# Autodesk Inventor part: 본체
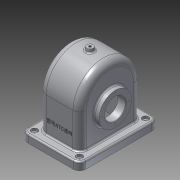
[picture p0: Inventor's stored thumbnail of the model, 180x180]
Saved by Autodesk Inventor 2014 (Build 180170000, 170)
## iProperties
Created: 2016-10
Part Number: 본체
Material: 알루미늄 6061
Document SubType Name: Modeling
Designer: USER
Density: 2.71 g/cm^3
Appearance: 알루미늄 - 평지
Mass: 1165.58 g
Surface Area: 1201.06 cm^2
Volume: 430.103 cm^3
Author: USER
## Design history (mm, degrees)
sketch "스케치2"
  geometry: L1 (-58, -80)-(58, -80); L2 (-58, 0)-(-58, -80); L3 (58, 0)-(58, -80); C1 r 52 at (0, 0); A1 r 58 centre (0, 0) between (58, 0) and (-58, 0); 1 further point
  constraints: 6 end point, 2 centre point, 2 point on circle, 2 tangent, 1 coincident, 1 parallel, 1 perpendicular
  dimensions: "d2" = 104 diameter of C1; "d4" = 6 radial gap between concentric circles of A1 C1; "d6" = 80 distance from line of L1 point (0, 0); "d8" = 138 dimension on A1 L1 (derived); "d9" = 58 distance from line of L2 point (0, 0) (derived); "d10" = 116 distance between parallel lines of L3 L2 (derived)
extrude "돌출1" new body sketch "스케치2" stored distance "d11" = 77; taper "d12" = 0 deg
fillet "모깎기1" dims "d13" = 13
sketch "스케치3"
  geometry: L1 (-58, -80)-(-58, 0) reference; L2 (58, 0)-(58, -80) reference; L3 (58, -80)-(-58, -80) reference; L4 (-52, 0)-(-52, -80); L5 (52, -80)-(52, 0); L6 (-52, -80)-(-52, -91.838); L7 (-52, -91.838)-(52, -91.838); L8 (52, -91.838)-(52, -80); A1 r 58 centre (0, 0) between (58, 0) and (-58, 0) reference; A2 r 52 centre (0, 0) between (52, 0) and (-52, 0); 1 further point
  constraints: 10 end point, 2 parallel, 2 point on circle, 2 point on line, 1 centre point, 1 perpendicular
  dimensions: "d14" = 6 radial gap between concentric circles of A1 A2; "d15" = 6 distance between parallel lines of L1 L4; "d16" = 6 distance between parallel lines of L2 L5
extrude "돌출2" cut sketch "스케치3" stored distance "d17" = 67; taper "d18" = 0 deg
fillet "모깎기2" dims "d19" = 8
sketch "스케치4"
  geometry: L1 (64, -13)-(64, -103) reference; L2 (51, 0)-(0, 0) reference; L3 (-13, -103)-(-13, -13) reference; L4 (0, -116)-(51, -116) reference; L5 (-29.5, -133)-(80.5, -133); L6 (80.5, -133)-(80.5, 17); L7 (80.5, 17)-(-29.5, 17); L8 (-29.5, 17)-(-29.5, -133); L9 (-29.5, -133)-(80.5, 17); L10 (80.5, -133)-(-29.5, 17); A1 r 13 centre (51, -103) between (51, -116) and (64, -103) reference; A2 r 13 centre (51, -13) between (64, -13) and (51, 0) reference; A3 r 13 centre (0, -13) between (0, 0) and (-13, -13) reference; A4 r 13 centre (0, -103) between (-13, -103) and (0, -116) reference; 3 further points
  constraints: 12 end point, 3 midpoint, 2 parallel, 1 coincident, 1 horizontal, 1 perpendicular
  dimensions: "d20" = 150 distance of L5.end L6.end; "d21" = 110 distance of L6.end L7.end
extrude "돌출3" join sketch "스케치4" distance "d22" = 15; taper "d23" = 0 deg
fillet "모깎기3" dims "d24" = 12
sketch "스케치5"
  geometry: A1 r 12 centre (-68.5, 5) between (-68.5, 17) and (-80.5, 5) reference; A2 r 12 centre (-68.5, -121) between (-80.5, -121) and (-68.5, -133) reference; A3 r 12 centre (17.5, -121) between (17.5, -133) and (29.5, -121) reference; A4 r 12 centre (17.5, 5) between (29.5, 5) and (17.5, 17) reference; 1 further point
hole "구멍1" sketch "스케치5" at (17.5, 5), (17.5, -121), (-68.5, -121), (-68.5, 5) diameter "d25" = 5; stored, may be unused: countersink angle "d29" = 90 deg, drill point angle "d31" = 118 deg; dims "d26" = 6, "d27" = 12, "d28" = 5, "d30" = 8
sketch "스케치6"
  geometry: L1 (-25.5, 58)-(25.5, 58) reference; L2 (38.5, 45)-(38.5, -65) reference; L3 (38.5, -65)-(55, -65) reference; L4 (55, -65)-(55, -80) reference; L5 (55, -80)-(33.5, -80) reference; L6 (33.5, -80)-(33.5, 44) reference; L7 (25.5, 52)-(-25.5, 52) reference; L8 (-33.5, 44)-(-33.5, -80) reference; L9 (-33.5, -80)-(-55, -80) reference; L10 (-55, -80)-(-55, -65) reference; L11 (-55, -65)-(-38.5, -65) reference; L12 (-38.5, -65)-(-38.5, 45) reference; L13 (-7.058, 58)-(-6, 64); L14 (-6, 64)-(0, 64); L15 (0, 0)-(0, 86.343); L16 (-7.058, 58)-(0, 58); L17 (-7.058, 58)-(-7.729, 54.192); L18 (-7.729, 54.192)-(0, 54.192); A1 r 13 centre (-25.5, 45) between (-25.5, 58) and (-38.5, 45) reference; A2 r 13 centre (25.5, 45) between (38.5, 45) and (25.5, 58) reference; A3 r 8 centre (25.5, 44) between (33.5, 44) and (25.5, 52) reference; A4 r 8 centre (-25.5, 44) between (-25.5, 52) and (-33.5, 44) reference
  constraints: 12 end point, 4 point on line, 2 perpendicular, 1 collinear, 1 midpoint, 1 parallel
  dimensions: "d32" = 33.5 distance from line of L8 L15.end (derived); "d33" = 100 deg angle of L1 L13; "d35" = 12 diameter of L13.end L15; "d36" = 144 distance between parallel lines of L5 L14
revolve "회전1" sketch "스케치6" stored, may be unused: angle "d37" = 90 deg
sketch "스케치7"
  geometry: L1 (38.5, -15)-(43.5, -15); L2 (-43, -80)-(-55, -80) reference; L3 (-25.5, 58)-(-7.058, 58) reference; L4 (-7.058, 58)-(-6, 64) reference; L5 (-6, 64)-(6, 64) reference; L6 (6, 64)-(7.058, 58) reference; L7 (7.058, 58)-(25.5, 58) reference; L8 (38.5, 45)-(38.5, -65) reference; L9 (38.5, -65)-(55, -65) reference; L10 (55, -65)-(55, -80) reference; L11 (55, -80)-(33.5, -80) reference; L12 (33.5, -80)-(33.5, 44) reference; L13 (25.5, 52)-(-25.5, 52) reference; L14 (-33.5, 44)-(-33.5, -80) reference; L15 (-33.5, -80)-(-55, -80) reference; L16 (-55, -80)-(-55, -65) reference; L17 (-55, -65)-(-38.5, -65) reference; L18 (-38.5, -65)-(-38.5, 45) reference; L19 (43.5, -15)-(43.5, 22.5); L20 (43.5, 22.5)-(38.5, 22.5); L21 (38.5, 22.5)-(38.5, -15); A1 r 13 centre (-25.5, 45) between (-25.5, 58) and (-38.5, 45) reference; A2 r 13 centre (25.5, 45) between (38.5, 45) and (25.5, 58) reference; A3 r 8 centre (25.5, 44) between (33.5, 44) and (25.5, 52) reference; A4 r 8 centre (-25.5, 44) between (-25.5, 52) and (-33.5, 44) reference; 3 further points
  constraints: 8 end point, 4 point on line, 1 collinear, 1 horizontal, 1 parallel, 1 perpendicular
  dimensions: "d38" = 65 distance between parallel lines of L2 L1; "d52" = 5 distance from line of L8 L1.end; "d53" = 75 diameter of L20 L1
revolve "회전3" sketch "스케치7" stored, may be unused: angle "d56" = 90 deg
sketch "스케치8"
  geometry: L1 (-25.5, 58)-(-7.058, 58) reference; L2 (-7.058, 58)-(-6, 64) reference; L3 (-6, 64)-(6, 64) reference; L4 (6, 64)-(7.058, 58) reference; L5 (7.058, 58)-(25.5, 58) reference; L6 (38.5, 45)-(38.5, 22.5) reference; L7 (38.5, 22.5)-(43.5, 22.5) reference; L8 (43.5, 22.5)-(43.5, -52.5) reference; L9 (43.5, -52.5)-(38.5, -52.5) reference; L10 (38.5, -52.5)-(38.5, -65) reference; L11 (38.5, -65)-(55, -65) reference; L12 (55, -65)-(55, -80) reference; L13 (55, -80)-(33.5, -80) reference; L14 (33.5, -80)-(33.5, 44) reference; L15 (25.5, 52)-(-25.5, 52) reference; L16 (-33.5, 44)-(-33.5, -80) reference; L17 (-33.5, -80)-(-55, -80) reference; L18 (-55, -80)-(-55, -65) reference; L19 (-55, -65)-(-38.5, -65) reference; L20 (-38.5, -65)-(-38.5, 45) reference; L21 (18.066, -15)-(-48.5, -15); L22 (-38.5, 16)-(-48.5, 16); L23 (-48.5, 16)-(-48.5, -15); L24 (-38.5, 16)-(-38.5, -15); A1 r 13 centre (-25.5, 45) between (-25.5, 58) and (-38.5, 45) reference; A2 r 13 centre (25.5, 45) between (38.5, 45) and (25.5, 58) reference; A3 r 8 centre (25.5, 44) between (33.5, 44) and (25.5, 52) reference; A4 r 8 centre (-25.5, 44) between (-25.5, 52) and (-33.5, 44) reference; 1 further point
  constraints: 8 end point, 3 point on line, 2 perpendicular, 1 parallel
  dimensions: "d57" = 65 distance between parallel lines of L17 L21; "d58" = 62 diameter of L22 L21; "d59" = 87 distance between parallel lines of L6 L23
revolve "회전4" sketch "스케치8" stored, may be unused: angle "d60" = 90 deg
sketch "스케치9"
  geometry: C1 r 31 at (0, 0) reference; 1 further point
hole "구멍2" sketch "스케치9" at (0, 0) diameter "d61" = 40; stored, may be unused: countersink angle "d65" = 90 deg, drill point angle "d67" = 118 deg; dims "d62" = 6, "d63" = 12, "d64" = 5, "d66" = 8
sketch "스케치10" dims "d68" = 52
  geometry: L1 (0, 0)-(26, 0); C1 r 20 at (0, 0) reference; C2 r 31 at (0, 0) reference; 2 further points
  constraints: 2 coincident, 2 end point, 1 horizontal, 1 horizontal alignment, 2 other
hole "구멍3" sketch "스케치10" at (26, 0), (0, 0), (-15, 0) diameter "d69" = 2.459; stored, may be unused: countersink angle "d73" = 90 deg, drill point angle "d75" = 118 deg; dims "d70" = 6, "d71" = 12, "d72" = 5, "d74" = 8
sketch "스케치11" dims "d79" = 58
  geometry: L1 (0, 0)-(-29, 0); C1 r 20 at (0, 0) reference; 2 further points
  constraints: 2 coincident, 2 end point, 1 horizontal, 1 horizontal alignment, 2 other
hole "구멍4" sketch "스케치11" at (-29, 0) diameter "d80" = 2.459; stored, may be unused: countersink angle "d84" = 90 deg, drill point angle "d86" = 118 deg; dims "d81" = 6, "d82" = 12, "d83" = 5, "d85" = 8
sketch "스케치12"
  geometry: C1 r 6 at (0, 0) reference
hole "구멍5" sketch "스케치12" at (0, 0) diameter "d90" = 4.459; stored, may be unused: countersink angle "d94" = 90 deg, drill point angle "d96" = 118 deg; dims "d91" = 6, "d92" = 12, "d93" = 5, "d95" = 8
fillet "모깎기4" dims "d97" = 3
sketch "스케치13"
  geometry: L1 (-13, 0)-(-13, -62) reference; L2 (68.5, -80)-(-17.5, -80) reference; 2 further points
  constraints: 1 other
  dimensions: "d98" = 38.5 distance from line of L1 point (25.5, -40); "d99" = 40 distance from line of L2 point (25.5, -40)
feature "엠보싱1" sketch "스케치13" dims "d100" = 0.5, "d101" = 0
sketch "스케치14"
  geometry: L1 (-48.5, -35)-(-33.5, -35) reference; L2 (-33.5, -35)-(-33.5, -80) reference; L3 (-33.5, -80)-(-55, -80) reference; L4 (-55, -80)-(-55, -68) reference; L5 (-52, -65)-(-41.5, -65) reference; L6 (-38.5, -62)-(-38.5, -49) reference; L7 (-41.5, -46)-(-48.5, -46) reference; L8 (-48.5, -46)-(-48.5, -42.229) reference; L9 (-48.5, -42.229)-(-40.5, -42.229) reference; L10 (-40.5, -42.229)-(-39.761, -41) reference; L11 (-39.761, -41)-(-40.5, -39.77) reference; L12 (-40.5, -39.77)-(-48.5, -39.77) reference; L13 (-48.5, -39.77)-(-48.5, -35) reference; L14 (33.5, -35)-(43.5, -35) reference; L15 (43.5, -35)-(43.5, -42.77) reference; L16 (43.5, -42.77)-(35.5, -42.77) reference; L17 (35.5, -42.77)-(34.761, -44) reference; L18 (34.761, -44)-(35.5, -45.229) reference; L19 (35.5, -45.229)-(43.5, -45.229) reference; L20 (43.5, -45.229)-(43.5, -52.5) reference; L21 (43.5, -52.5)-(41.5, -52.5) reference; L22 (38.5, -55.5)-(38.5, -62) reference; L23 (41.5, -65)-(52, -65) reference; L24 (55, -68)-(55, -80) reference; L25 (55, -80)-(33.5, -80) reference; L26 (33.5, -80)-(33.5, -35) reference; L27 (25.5, 52)-(2.229, 52) reference; L28 (2.229, 52)-(2.229, 64) reference; L29 (2.229, 64)-(6, 64) reference; L30 (6, 64)-(6.621, 60.479) reference; L31 (9.575, 58)-(25.5, 58) reference; L32 (38.5, 45)-(38.5, 25.5) reference; L33 (41.5, 22.5)-(43.5, 22.5) reference; L34 (43.5, 22.5)-(43.5, 15.23) reference; L35 (43.5, 15.23)-(35.5, 15.23) reference; L36 (35.5, 15.23)-(34.761, 14) reference; L37 (34.761, 14)-(35.5, 12.771) reference; L38 (35.5, 12.771)-(43.5, 12.771) reference; L39 (43.5, 12.771)-(43.5, 5) reference; L40 (43.5, 5)-(33.5, 5) reference; L41 (33.5, 5)-(33.5, 44) reference; L42 (-33.5, 44)-(-33.5, 5) reference; L43 (-33.5, 5)-(-48.5, 5) reference; L44 (-48.5, 5)-(-48.5, 9.771) reference; L45 (-48.5, 9.771)-(-40.5, 9.771) reference; L46 (-40.5, 9.771)-(-39.761, 11) reference; L47 (-39.761, 11)-(-40.5, 12.23) reference; L48 (-40.5, 12.23)-(-48.5, 12.23) reference; L49 (-48.5, 12.23)-(-48.5, 16) reference; L50 (-48.5, 16)-(-41.5, 16) reference; L51 (-38.5, 19)-(-38.5, 45) reference; L52 (-25.5, 58)-(-9.575, 58) reference; L53 (-6.621, 60.479)-(-6, 64) reference; L54 (-6, 64)-(-2.229, 64) reference; L55 (-2.229, 64)-(-2.229, 52) reference; L56 (-2.229, 52)-(-25.5, 52) reference; L57 (33.5, 24.747)-(19.5, 13); L58 (19.5, 13)-(19.5, -15); L59 (-48.5, -35)-(-33.5, -35) reference; L60 (-33.5, -35)-(-33.5, -80) reference; L61 (-33.5, -80)-(-55, -80) reference; L62 (-55, -80)-(-55, -68) reference; L63 (-52, -65)-(-41.5, -65) reference; L64 (-38.5, -62)-(-38.5, -49) reference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; A1 r 3 centre (-52, -68) between (-52, -65) and (-55, -68) reference; A2 r 3 centre (-41.5, -62) between (-41.5, -65) and (-38.5, -62) reference; A3 r 3 centre (-41.5, -49) between (-38.5, -49) and (-41.5, -46) reference; A4 r 3 centre (41.5, -55.5) between (41.5, -52.5) and (38.5, -55.5) reference; A5 r 3 centre (41.5, -62) between (38.5, -62) and (41.5, -65) reference; A6 r 3 centre (52, -68) between (55, -68) and (52, -65) reference; A7 r 8 centre (25.5, 44) between (33.5, 44) and (25.5, 52) reference; A8 r 13 centre (25.5, 45) between (38.5, 45) and (25.5, 58) reference; A9 r 3 centre (41.5, 25.5) between (38.5, 25.5) and (41.5, 22.5) reference; A10 r 8 centre (-25.5, 44) between (-25.5, 52) and (-33.5, 44) reference; A11 r 3 centre (-41.5, 19) between (-41.5, 16) and (-38.5, 19) reference; A12 r 13 centre (-25.5, 45) between (-25.5, 58) and (-38.5, 45) reference; A13 r 3 centre (-52, -68) between (-52, -65) and (-55, -68) reference; A14 r 3 centre (-41.5, -62) between (-41.5, -65) and (-38.5, -62) reference; A15 r 3 centre (-41.5, -49) between (-38.5, -49) and (-41.5, -46) reference; A16 r 3 centre (41.5, -55.5) between (41.5, -52.5) and (38.5, -55.5) reference; A17 r 3 centre (41.5, -62) between (38.5, -62) and (41.5, -65) reference; A18 r 3 centre (52, -68) between (55, -68) and (52, -65) reference; A19 r 8 centre (25.5, 44) between (33.5, 44) and (25.5, 52) reference; A20 r 13 centre (25.5, 45) between (38.5, 45) and (25.5, 58) reference; A21 r 3 centre (41.5, 25.5) between (38.5, 25.5) and (41.5, 22.5) reference; A22 r 8 centre (-25.5, 44) between (-25.5, 52) and (-33.5, 44) reference; A23 r 3 centre (-41.5, 19) between (-41.5, 16) and (-38.5, 19) reference; A24 r 13 centre (-25.5, 45) between (-25.5, 58) and (-38.5, 45) reference; A25 r 3 centre (-52, -68) between (-52, -65) and (-55, -68) reference; A26 r 3 centre (-41.5, -62) between (-41.5, -65) and (-38.5, -62) reference; A27 r 3 centre (-41.5, -49) between (-38.5, -49) and (-41.5, -46) reference; A28 r 3 centre (41.5, -55.5) between (41.5, -52.5) and (38.5, -55.5) reference; A29 r 3 centre (41.5, -62) between (38.5, -62) and (41.5, -65) reference; A30 r 3 centre (52, -68) between (55, -68) and (52, -65) reference; A31 r 8 centre (25.5, 44) between (33.5, 44) and (25.5, 52) reference; A32 r 13 centre (25.5, 45) between (38.5, 45) and (25.5, 58) reference; A33 r 3 centre (41.5, 25.5) between (38.5, 25.5) and (41.5, 22.5) reference; A34 r 8 centre (-25.5, 44) between (-25.5, 52) and (-33.5, 44) reference; A35 r 3 centre (-41.5, 19) between (-41.5, 16) and (-38.5, 19) reference; A36 r 13 centre (-25.5, 45) between (-25.5, 58) and (-38.5, 45) reference; 1 further point
  constraints: 10 end point, 3 perpendicular, 1 midpoint, 1 parallel, 1 point on circle, 1 point on line, 6 other
  dimensions: "d102" = 56 diameter of L57.end L172; "d103" = 50 deg angle of L58 L57; "d104" = 24 distance between parallel lines of L97 L58
revolve "회전5" sketch "스케치14" stored, may be unused: angle "d105" = 90 deg
sketch "스케치15"
  geometry: C1 r 20 at (0, 0) reference; 1 further point
extrude "돌출4" cut sketch "스케치15" stored distance "d106" = 15; taper "d107" = 0 deg
sketch "스케치16"
  geometry: 1 further point
fillet "모깎기5" dims "d108" = 3
chamfer "모따기1" distance "d109" = 1; stored, may be unused: second distance "d110" = 2, angle "d111" = 45 deg
chamfer "모따기2" distance "d112" = 1; stored, may be unused: second distance "d113" = 2, angle "d114" = 45 deg
node "솔리드1"
pattern_circular "원형 패턴1" dims angle "d77" = 360 deg
pattern_circular "원형 패턴2" dims angle "d88" = 360 deg
node "절단 모서리 투영1"
node "절단 모서리 투영2"
node "절단 모서리 투영3"
node "절단 모서리 투영4"
node "절단 모서리 투영5"
node "절단 모서리 투영6"
node "절단 모서리 투영7"
